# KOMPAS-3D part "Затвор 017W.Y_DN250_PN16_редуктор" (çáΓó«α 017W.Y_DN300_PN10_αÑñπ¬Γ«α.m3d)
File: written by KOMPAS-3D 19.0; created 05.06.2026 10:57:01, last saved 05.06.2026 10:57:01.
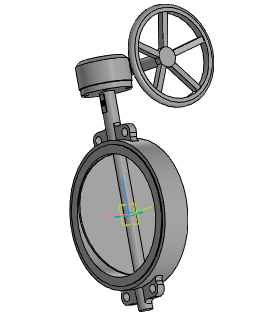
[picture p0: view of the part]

Document properties: Автор: Энергия; Полное имя файла: ..\..\..\3d для проектировщиков\x.x Тип 017W.Y(S) Затвор дисковый поворотный межфланцевый\Затвор 017W.Y(S)_DN50-DN1200_редуктор\Затвор 017W.Y_DN300_PN10_редуктор.a3d

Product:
- Part/product: Затвор 017W.Y_DN250_PN16_редуктор
    Масса: 39.0805

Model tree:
1. Операция без истории:1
